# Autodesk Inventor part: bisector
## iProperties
Shininess: 64.0
Length Units: 11272
Angle Units: 11279
Time Units: 11290
Mass Units: 11286
Length Display Precision: 3
Angle Display Precision: 2
Compacted: True
Part Number: bisector
Document SubType Name: Modeling
Created: 2002-11
Designer: Elise Moss
Density: 0.0
Volumn: 0.0
Area: 0.0
PropertySet Name: Model Information
Control State: 0
Master: False
Checked Out: False
Author: Elise Moss
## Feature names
1. Extrusion1
